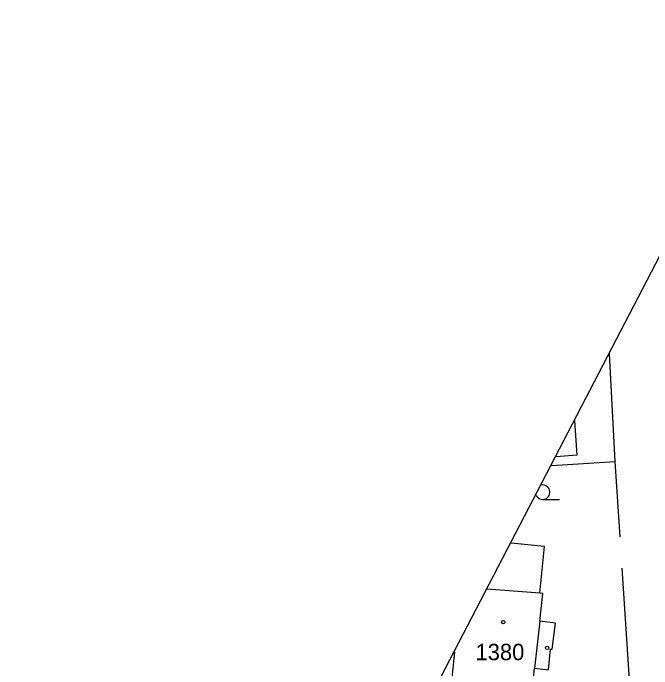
# Model space of a CAD drawing. Extents: x -781083 to -763634, y -1029516 to -1022695.
# Drawn here: x -765063.6 to -764997.5, y -1023752.9 to -1023685 of the extents above; entities that cross this region are included whole.
import ezdxf

# ---------------------------------------------------------------- set-up
doc = ezdxf.new("R2010")
doc.units = 0
for name, color, linetype in [('Hranice parcel', 7, 'Continuous'), ('Parcelní čísla', 7, 'Continuous'), ('Vnitřní kresba', 7, 'Continuous'), ('Značky budov', 7, 'Continuous'), ('Značky kultur', 7, 'Continuous')]:
    doc.layers.add(name, color=color, linetype=linetype)

# ---------------------------------------------------------------- blocks, each defined once
blk = doc.blocks.new('4.02')
at = {"layer": 'Značky budov'}
blk.add_circle((-0.07, 0.01), 1.75, dxfattribs=at)

msp = doc.modelspace()

# ---------------------------------------------------------------- linework, layer by layer
msp.add_lwpolyline([(-765336.117, -1024363.479), (-765204.05, -1024432.093), (-764769.725, -1023596.107), (-764901.792, -1023527.494)], close=True)
at = {"layer": 'Hranice parcel'}
for p, q in [((-765001.26, -1023731.45), (-765001.852, -1023720.292)), ((-765007.865, -1023731.866), (-765001.26, -1023731.45)), ((-765000.754, -1023739.258), (-765001.26, -1023731.45)), ((-764999.76, -1023754.6), (-765000.543, -1023742.51))]:
    msp.add_line(p, q, dxfattribs=at)
for points in [[(-765009.93, -1023755.72), (-765009.62, -1023752.85), (-765008.16, -1023753.01), (-765007.95, -1023750.88), (-765007.79, -1023750.9), (-765007.45, -1023748.18), (-765009.08, -1023748), (-765008.76, -1023745.13), (-765009.06, -1023745.1), (-765008.59, -1023740.25), (-765012.044, -1023739.911)], [(-765017.912, -1023751.205), (-765018.31, -1023755.15)]]:
    msp.add_lwpolyline(points, dxfattribs=at)
at = {"layer": 'Vnitřní kresba'}
for p, q in [((-765005.21, -1023730.8), (-765005.439, -1023727.197)), ((-765005.21, -1023730.8), (-765007.402, -1023730.976)), ((-765009.06, -1023745.1), (-765014.511, -1023744.66)), ((-765009.08, -1023748), (-765009.38, -1023750.72)), ((-765009.38, -1023750.72), (-765009.62, -1023752.85))]:
    msp.add_line(p, q, dxfattribs=at)
at = {"layer": 'Značky kultur'}
msp.add_line((-765008.773, -1023735.37), (-765007.023, -1023735.37), dxfattribs=at)
msp.add_arc((-765008.773, -1023734.62), 0.75, 204.35789, 100.73508, dxfattribs=at)

# ---------------------------------------------------------------- block references
at = {"layer": 'Značky budov', "xscale": 0.1, "yscale": 0.10000000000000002}
for p in [(-765012.85, -1023748.08), (-765008.3, -1023750.76)]:
    msp.add_blockref('4.02', p, dxfattribs=at)

# ---------------------------------------------------------------- texts
at = {"layer": 'Parcelní čísla'}
msp.add_text('1380', height=1.7, dxfattribs=at).set_placement((-765015.73, -1023752.03))

doc.saveas('drawing.dxf')
